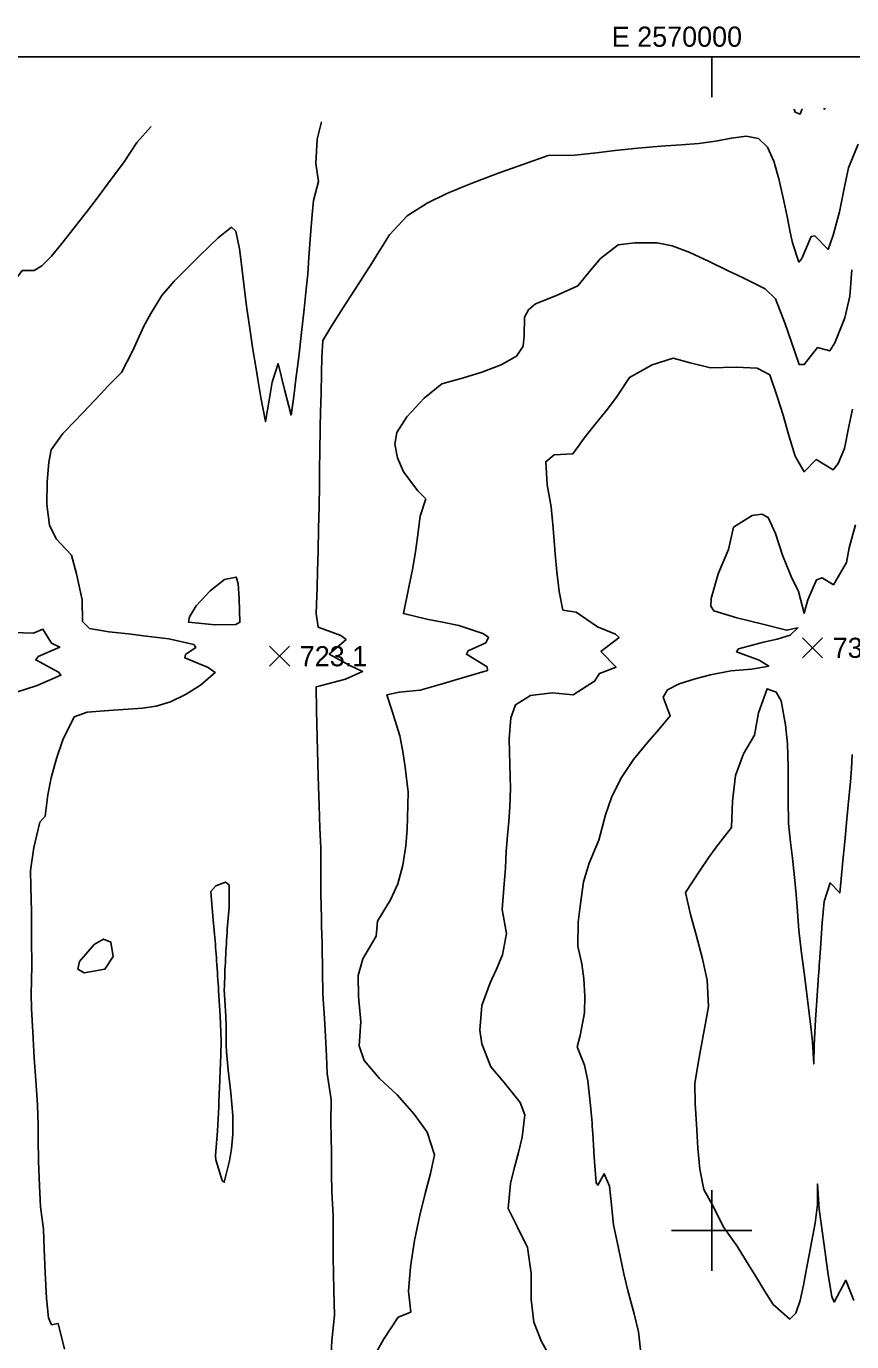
# Model space of a CAD drawing. Extents: x 2566079 to 2571326, y 424054 to 426896.
# Drawn here: x 2569490 to 2570104, y 425917 to 426896 of the extents above; entities that cross this region are included whole.
import ezdxf

# ---------------------------------------------------------------- set-up
doc = ezdxf.new("R2010")
doc.units = 0
for name, color, linetype in [('Contour_ADS_Major', 7, 'Continuous'), ('Contour_ADS_Minor', 7, 'Continuous'), ('Contour_ADS_Spot_Elevation', 7, 'Continuous'), ('Contour_ADS_State_Plane_Border', 7, 'Continuous'), ('Contour_ADS_Tick', 7, 'Continuous')]:
    doc.layers.add(name, color=color, linetype=linetype)

# ---------------------------------------------------------------- blocks, each defined once
blk = doc.blocks.new('S890')
at = {"layer": 'Contour_ADS_Tick'}
for p, q in [((0, -0.5), (0, 0.5)), ((-0.5, 0), (0.5, 0))]:
    blk.add_line(p, q, dxfattribs=at)
blk = doc.blocks.new('S750')
at = {"layer": 'Contour_ADS_Spot_Elevation'}
for p, q in [((-0.5, 0.498), (0.5, -0.498)), ((-0.498, -0.5), (0.498, 0.5))]:
    blk.add_line(p, q, dxfattribs=at)

msp = doc.modelspace()

# ---------------------------------------------------------------- linework, layer by layer
at = {"layer": 'Contour_ADS_Major'}
for points in [[(2569582.66, 426821.92), (2569572.1, 426809.88), (2569562, 426794.76), (2569552.24, 426781.55), (2569544.76, 426771.47), (2569537.76, 426762.19), (2569528.08, 426749.94), (2569516.18, 426734.74), (2569508.52, 426725.45), (2569501.28, 426718.14), (2569495.52, 426714.64), (2569486.72, 426714.73), (2569480.41, 426706.26), (2569473.21, 426694.62), (2569463.96, 426679.49), (2569454.21, 426663.45), (2569445.24, 426648.69), (2569437.29, 426635.75), (2569434.53, 426631.41)], [(2570107.12, 426525.37), (2570102.32, 426508.18), (2570100.29, 426497.28), (2570090.65, 426480.65), (2570082.37, 426485.87), (2570078.05, 426484.34), (2570071.67, 426469.57), (2570068.78, 426459.47), (2570064.64, 426475.67), (2570059.19, 426486.97), (2570052.74, 426502.72), (2570047.41, 426518.79), (2570042.09, 426530.89), (2570037.29, 426533.31), (2570030.17, 426532.38), (2570016.35, 426523.68), (2570012.52, 426506.83), (2570004.76, 426488.72), (2569999.65, 426470.57), (2569999.44, 426464.75), (2570001.54, 426461.17), (2570018.68, 426456.18), (2570038.05, 426451.34), (2570055.76, 426446.84), (2570064.26, 426448.59), (2570058.38, 426443.29), (2570048.7, 426440.29), (2570038.58, 426438.04), (2570020.06, 426433.05), (2570018.41, 426430.88), (2570035.43, 426424.44), (2570042.51, 426420.21), (2570029.91, 426417.98), (2570014.18, 426416.52), (2569999.15, 426413.54), (2569987.7, 426410.75), (2569975.82, 426407.02), (2569967.05, 426402.4), (2569963.91, 426397.09), (2569969.05, 426383.2), (2569960.7, 426372.88), (2569952.14, 426363.3), (2569941.91, 426350.7), (2569932.39, 426336.52), (2569925.45, 426322.22), (2569920.96, 426309.42), (2569916.1, 426290.63), (2569908.68, 426273.47), (2569904.6, 426259.45), (2569902.03, 426241.54), (2569900.53, 426229.44), (2569900.28, 426211.65), (2569903.31, 426198.48), (2569904.69, 426187.43), (2569905.44, 426174.38), (2569905.24, 426161.93), (2569902.14, 426145.04), (2569899.79, 426136.61), (2569905.4, 426123.02), (2569907.81, 426111.48), (2569909.86, 426093.09)], [(2569479.69, 426445.26), (2569495.15, 426444.69), (2569502.07, 426447.75), (2569508.42, 426437.31), (2569514.67, 426434.18), (2569498.58, 426427.32), (2569496.72, 426424.79), (2569513.76, 426415.67), (2569515.44, 426413.39), (2569497.72, 426405.76), (2569481.61, 426400.43)], [(2569911.43, 426072.18), (2569912.44, 426054.5), (2569913.89, 426035.45), (2569915.24, 426033.6), (2569920.05, 426042.2), (2569923.8, 426032.86), (2569925.23, 426021.36), (2569927, 426004.26), (2569929.52, 425991.51), (2569931.76, 425980.91), (2569934.63, 425967.81), (2569937.6, 425955.23), (2569942.4, 425937.97), (2569945.45, 425924.57), (2569947.61, 425906.62)]]:
    msp.add_lwpolyline(points, dxfattribs=at)
msp.add_arc((2569084.33, 426020.59), 828.71, 3.56903, 5.01882, dxfattribs=at)
at = {"layer": 'Contour_ADS_Minor'}
msp.add_line((2569638.3, 426159.62), (2569637.12, 426179.21), dxfattribs=at)
for points in [[(2570067.45, 426834.97), (2570065.76, 426831.1), (2570062.22, 426832.51), (2570061.32, 426834.81)], [(2570084.69, 426835.44), (2570083.91, 426834.76), (2570083.13, 426835.39)], [(2569709.55, 426825.34), (2569706.38, 426812.32), (2569705.36, 426794.34), (2569707.35, 426780.87), (2569703.51, 426766.87), (2569702.55, 426756.44), (2569701.59, 426744.3), (2569700.16, 426724.67), (2569699.23, 426712.03), (2569698.14, 426700.72), (2569696.6, 426685.76), (2569694.69, 426668.47), (2569692.55, 426650.37), (2569690.49, 426633.69), (2569688.84, 426620.81), (2569686.88, 426607.03), (2569681.86, 426626.19), (2569677.17, 426645.42), (2569672.83, 426631.49), (2569670.52, 426618.05), (2569667.89, 426602.13), (2569664.32, 426620.03), (2569662.13, 426633.59), (2569660.55, 426642.89), (2569658.45, 426655.85), (2569656.07, 426671.47), (2569653.74, 426688.18), (2569651.71, 426704.47), (2569649.98, 426719.1), (2569648.46, 426730.9), (2569645.67, 426743.9), (2569642.4, 426746.85), (2569632.52, 426739.01), (2569626.69, 426733.27), (2569618.02, 426724.8), (2569608.28, 426715.25), (2569599.81, 426706.79), (2569590.61, 426696.16), (2569582.46, 426682.67), (2569577.26, 426673.22), (2569568.95, 426655.09), (2569560.71, 426638.74), (2569550.56, 426628.84), (2569545.23, 426622.82), (2569536.37, 426613.46), (2569526, 426602.76), (2569516.91, 426593.4), (2569508.13, 426581.06), (2569506.43, 426571.94), (2569505.13, 426557.37), (2569504.96, 426540.34), (2569507.06, 426525.14), (2569512.01, 426514.94), (2569523.41, 426502.63), (2569527.04, 426488.86), (2569531.19, 426469.48), (2569531.45, 426453.39), (2569536.86, 426448.02), (2569551.26, 426445.57), (2569565.76, 426444.11), (2569578.84, 426442.37), (2569595.92, 426440.33), (2569614.44, 426436.28), (2569616.03, 426434.05), (2569608.12, 426428.66), (2569607.76, 426426.25), (2569625.14, 426419.14), (2569630.37, 426415.49), (2569619.34, 426405.93), (2569608.68, 426399.17), (2569597.19, 426393.46), (2569586.44, 426390.2), (2569576.17, 426388.8), (2569565.64, 426388.17), (2569554.47, 426387.43), (2569535.06, 426385.81), (2569525.34, 426382.45), (2569517.02, 426365.35), (2569512.15, 426351.38), (2569508.17, 426336.97), (2569505.86, 426324.38), (2569503.85, 426308.38), (2569499.74, 426303.87), (2569495.3, 426285.04), (2569492.9, 426267.88), (2569493.15, 426256.06), (2569493.47, 426237.45)], [(2570108.97, 426808.71), (2570101.79, 426791.01), (2570098.87, 426776.97), (2570095.22, 426758.32), (2570090.35, 426741.04), (2570086.69, 426730.37), (2570076.82, 426740.4), (2570074.1, 426740.09), (2570067.15, 426723.68), (2570064.92, 426720.9), (2570060.11, 426735.18), (2570058.53, 426743.19), (2570056.2, 426754.8), (2570053.24, 426768.67), (2570049.9, 426783.02), (2570046.2, 426796.11), (2570041.45, 426806.55), (2570034.8, 426812.99), (2570025.65, 426814.68), (2570014.66, 426813.23), (2570002.73, 426810.86), (2569990.5, 426809.29), (2569977.32, 426808.32), (2569962.26, 426807.29), (2569945.03, 426805.71), (2569928.04, 426803.88), (2569914.34, 426802.3), (2569898.1, 426800.6), (2569878.29, 426800.27), (2569860.04, 426793.89), (2569842.52, 426787.54)], [(2569802.21, 426771.66), (2569788.16, 426764.76), (2569773.31, 426755.29), (2569760.2, 426741.21), (2569754.76, 426732.5), (2569746.97, 426720.11), (2569736.69, 426704.12), (2569725.9, 426687.48), (2569717.13, 426673.84), (2569710.37, 426662.44), (2569709.77, 426650.2), (2569709.51, 426638.17), (2569709.18, 426623.45), (2569708.86, 426609.28), (2569708.58, 426598.05), (2569708.2, 426579.13), (2569708.06, 426567.83), (2569707.9, 426554.51), (2569707.67, 426539.27), (2569707.33, 426522.49), (2569706.93, 426505.67), (2569706.53, 426490.63), (2569706.2, 426478.81), (2569705.63, 426459.22), (2569707.14, 426449.07), (2569723.86, 426442.86), (2569727.78, 426439.87), (2569715.29, 426428.99), (2569730.49, 426420.67), (2569740.12, 426416.15), (2569727.43, 426410.32), (2569708.41, 426405.52), (2569705.47, 426404.64), (2569705.77, 426387.6), (2569706.04, 426376.8), (2569706.47, 426357.04), (2569706.91, 426338.45), (2569707.21, 426330.5), (2569707.73, 426316.33), (2569708.35, 426299.54), (2569708.89, 426284.93), (2569708.99, 426264.94), (2569709.11, 426250.32), (2569709.45, 426232.62)], [(2570104.36, 426715.06), (2570102.83, 426695.65), (2570099.14, 426679.48), (2570091.73, 426660.91), (2570087.85, 426654.75), (2570078.86, 426657.27), (2570068.92, 426644.58), (2570065.21, 426644.58), (2570058.84, 426662.76), (2570054.59, 426675.08), (2570047.51, 426693.67), (2570039.93, 426701.03), (2570023.42, 426709.22), (2570011.67, 426714.75), (2569998.05, 426721.43), (2569983.84, 426728.04), (2569970.55, 426733.03), (2569959.37, 426735.33), (2569942.68, 426735.32), (2569930.38, 426733.76), (2569917.22, 426723.58), (2569910.29, 426715.49), (2569900.27, 426703.37), (2569884.55, 426696.16), (2569868.88, 426689.84), (2569863.63, 426685.35), (2569860.7, 426679.86), (2569860.34, 426666.04), (2569859.6, 426658.33), (2569854.58, 426650.9), (2569843.38, 426644.32), (2569828.89, 426638.89), (2569815.16, 426634.84), (2569798.99, 426630.36), (2569785.9, 426619.54), (2569773.13, 426605.84), (2569765.51, 426594.09), (2569764.08, 426585.49), (2569766.12, 426575.22), (2569770.66, 426564.81), (2569781.3, 426550.59), (2569787.13, 426544.55), (2569783.05, 426531.88), (2569780.86, 426516.21), (2569779.46, 426505.19), (2569777.13, 426492.03), (2569774.42, 426478.82), (2569770.44, 426459.26), (2569787.97, 426455.02), (2569799.66, 426452.95), (2569811.64, 426450.36), (2569829.58, 426444.33), (2569833.85, 426441.58), (2569831.8, 426437.54), (2569818.59, 426431.45), (2569817.37, 426428.93), (2569832.91, 426419.58), (2569833.18, 426416.99), (2569816.9, 426412.08), (2569798.58, 426406.81), (2569783.07, 426402.33), (2569767.38, 426400.83), (2569758.23, 426398.87), (2569762.12, 426386.71), (2569767.71, 426368.28), (2569769.99, 426356.52), (2569771.74, 426344.9), (2569773.94, 426326.23), (2569773.61, 426307.51), (2569773.18, 426298.67), (2569772.18, 426286.27), (2569770.1, 426271.97), (2569766.38, 426257.99), (2569760.88, 426246.21), (2569751.12, 426230.34), (2569750.28, 426218.99), (2569740.23, 426202.21), (2569736.76, 426189.8), (2569737.03, 426174.1), (2569738.8, 426155.64), (2569737.44, 426137.51), (2569741.28, 426126.63), (2569752.78, 426113.18), (2569765.83, 426100.93), (2569778.6, 426086.6)], [(2570104.77, 426611.42), (2570102.21, 426598.45), (2570098.82, 426582.13), (2570094.19, 426571.05), (2570090.4, 426566.29), (2570077.83, 426574.01), (2570068.81, 426564.78), (2570062.23, 426576.36), (2570057.53, 426591.94), (2570053.23, 426607.02), (2570048.77, 426620.94), (2570043.33, 426636.87), (2570033.82, 426641.84), (2570018.33, 426642.73), (2569999.12, 426642.12), (2569983.87, 426645.89), (2569971.25, 426649.3), (2569955.58, 426644.45), (2569938.89, 426635.07), (2569929.67, 426621.14), (2569922.35, 426611.5), (2569913.58, 426600.6), (2569905.82, 426590.85), (2569896.5, 426578.11), (2569882.73, 426577.48), (2569876.41, 426572.25), (2569877.4, 426555.09), (2569880.54, 426538.75), (2569882.08, 426522.94), (2569883.58, 426503.61), (2569884.69, 426490.37), (2569886.56, 426475.67), (2569889.3, 426461.86), (2569899.15, 426460.36), (2569915.03, 426449.46), (2569928.39, 426443.89), (2569931.11, 426441.34), (2569917.51, 426431), (2569928.82, 426419.38), (2569916.36, 426414.67), (2569912.82, 426408.88), (2569896.94, 426398.66), (2569881.21, 426400.13), (2569865.06, 426398.32), (2569853.85, 426391.4), (2569850.44, 426381.6), (2569849.32, 426365.75), (2569849.63, 426346.89), (2569850.11, 426329.08), (2569849.81, 426315.36), (2569848.92, 426304.44), (2569847.89, 426293.99), (2569847.08, 426282.26), (2569846.39, 426269.84), (2569845.61, 426257.93)], [(2570079.59, 426189.88), (2570078.29, 426171.27), (2570077.25, 426156.69), (2570076.27, 426137.93), (2570076.03, 426123.97), (2570075.16, 426140.49), (2570073.89, 426151.53), (2570072.34, 426163.63), (2570070.47, 426178.25), (2570068.75, 426191.85), (2570066.71, 426208.51), (2570064.92, 426223.56), (2570063.6, 426240.63), (2570062.8, 426250.18), (2570061.56, 426263.1), (2570060.09, 426277.08), (2570058.74, 426289.06), (2570057.21, 426303.03), (2570056.95, 426320.77), (2570057.04, 426333.19), (2570057.03, 426345.1), (2570056.35, 426362.35), (2570055.04, 426376.31), (2570051.65, 426394.32), (2570048.01, 426400.84), (2570041.22, 426403.26), (2570034.93, 426385.36), (2570031.83, 426368.72), (2570023.62, 426354.73), (2570017.67, 426338.77), (2570015.61, 426319.62), (2570014.64, 426299.93), (2570003.25, 426285.42), (2569997.64, 426277.45), (2569991.43, 426268.24), (2569980.48, 426251.56), (2569984.28, 426235.13), (2569988.44, 426220.01), (2569993.1, 426202.2), (2569996.74, 426186.23), (2569997.71, 426166.84), (2569995.9, 426157.15), (2569993.39, 426143.62), (2569990.78, 426128.81), (2569987.49, 426109.66), (2569987.69, 426094.2), (2569988.58, 426079.13), (2569989.76, 426061.26), (2569991.08, 426045.69), (2569994.25, 426030.55), (2570000.25, 426019.26), (2570009.15, 426002.21), (2570018.88, 425988.22), (2570028.02, 425973.75), (2570033.29, 425964.92), (2570039.23, 425955.12), (2570045.84, 425944.91), (2570058.27, 425933.97), (2570062.64, 425938.29), (2570065.83, 425947.76), (2570068.3, 425959.25), (2570070.42, 425970.13), (2570073.67, 425987.13), (2570077.12, 426005.53), (2570078.8, 426019.43), (2570078.69, 426034.65), (2570079.95, 426015.9), (2570082.4, 425998.03), (2570084.41, 425983.69), (2570086.8, 425966.92), (2570089.52, 425950.87), (2570091.13, 425946.64), (2570099.84, 425962.89), (2570105.83, 425947.85)], [(2570104.58, 426354.36), (2570104.05, 426343.88), (2570103.27, 426333.91), (2570102.14, 426321.89), (2570100.63, 426306.29), (2570099.01, 426289.54), (2570097.63, 426275.05), (2570096.03, 426256.38), (2570095.4, 426251.25), (2570088.12, 426258.76), (2570083.69, 426244.82), (2570082.24, 426229.03), (2570080.95, 426209.96), (2570080.27, 426199.92)], [(2569639.35, 426224.25), (2569640.73, 426240.64), (2569640.79, 426257.19), (2569638.11, 426259.17), (2569630.8, 426256.53), (2569627.09, 426252.31), (2569628.63, 426233.88), (2569629.89, 426220.69)], [(2569845.61, 426257.93), (2569844.06, 426238.84), (2569847.12, 426221.07), (2569844.23, 426205.09), (2569839.83, 426194.5), (2569835.15, 426184.25), (2569828.75, 426167.5), (2569827.41, 426149.2), (2569828.78, 426138.93), (2569835.59, 426121.81), (2569845.42, 426110.09), (2569857.3, 426095.28), (2569860.78, 426086.12), (2569858.87, 426069.54), (2569856.17, 426058.01), (2569853.05, 426046.06), (2569850.17, 426034.87), (2569848.59, 426016.27), (2569855.49, 426002.49), (2569862.76, 425987.27), (2569865.51, 425968.22), (2569865.7, 425948.54), (2569867.65, 425931.76), (2569873.13, 425917.74), (2569880.37, 425904.06)], [(2569709.66, 426222.17), (2569709.88, 426211.73), (2569710.24, 426193.42), (2569710.52, 426176.2), (2569711.85, 426157.78), (2569712.49, 426144.71), (2569713.12, 426129.79), (2569713.62, 426116.94), (2569716.7, 426097.57), (2569716.56, 426079.79), (2569716.79, 426070.48), (2569716.9, 426057.09), (2569716.98, 426042.16), (2569717.16, 426028.96), (2569718.26, 426010.95), (2569718.14, 425994.54), (2569718.09, 425980.17), (2569718.33, 425968.28), (2569718.66, 425955.38), (2569719.11, 425937.01), (2569717.08, 425917.75), (2569716.4, 425902.97)], [(2569493.7, 426216.14), (2569493.75, 426197.62), (2569493.57, 426185.56), (2569493.44, 426176.45), (2569493.68, 426165.03), (2569494.53, 426147.77), (2569495.68, 426128.24), (2569496.71, 426111.78), (2569498.07, 426093.53), (2569498.44, 426078.05), (2569498.54, 426067.77), (2569498.91, 426051.6), (2569499.5, 426033.25), (2569500.22, 426017.61), (2569502.52, 426001.02), (2569503.12, 425986.19), (2569503.73, 425968.81), (2569504.76, 425949.47), (2569506.33, 425934.92), (2569508.52, 425929.78), (2569513.52, 425930.61), (2569518.25, 425911.56)], [(2569632.91, 426178.32), (2569634.1, 426159.68), (2569634.84, 426141.05), (2569634.49, 426130.53), (2569633.81, 426112.9)], [(2569630.82, 426052.52), (2569635.5, 426037.19), (2569637.05, 426035.83), (2569641.06, 426051.73), (2569642.46, 426060.78), (2569643.45, 426071.72), (2569643.44, 426085.51), (2569642.08, 426102.33), (2569639.97, 426119.42), (2569638.73, 426132.92)], [(2569632.95, 426092.11), (2569632.1, 426074.2), (2569630.53, 426055.79), (2569630.82, 426052.52), (2569630.82, 426052.52)], [(2569778.6, 426086.6), (2569788.23, 426073.11), (2569793.52, 426056.32), (2569790.55, 426042.43), (2569786.63, 426027.62), (2569782.59, 426011.26), (2569778.68, 425992.56), (2569775.73, 425972.99), (2569774.38, 425954.83), (2569775.93, 425939.19), (2569766.7, 425935.38), (2569755.74, 425918.92), (2569750.27, 425909.15)]]:
    msp.add_lwpolyline(points, dxfattribs=at)
for points in [[(2569647.38, 426481.59), (2569645.9, 426486.36), (2569637.3, 426484.7), (2569626.68, 426476.24), (2569616.18, 426465.09), (2569611.2, 426456.79), (2569610.6, 426452.77), (2569630.32, 426450.84), (2569645.82, 426451.02), (2569648.72, 426452.73), (2569648.2, 426470.3), (2569647.38, 426481.59)], [(2569528.09, 426194.62), (2569529.26, 426200.32), (2569540.22, 426213), (2569547.26, 426216.95), (2569552.63, 426214.72), (2569554.47, 426204.06), (2569548.3, 426194.59), (2569532.74, 426191.87), (2569528.09, 426194.62)]]:
    msp.add_lwpolyline(points, close=True, dxfattribs=at)
for centre, radius, start, end in [((2570240.36, 425701.55), 1156.57, 110.11948, 111.22666), ((2570001.19, 426316.08), 497.14, 111.17547, 113.59372), ((2566523.97, 426194.74), 2969.8, 0.4128, 0.82395), ((2585260.15, 426539.89), 15553.74, 181.131992, 181.170494), ((2567881.71, 426078.95), 1753.92, 3.97849, 4.63533), ((2570710.05, 426151.71), 1073.16, 176.12403, 177.29629), ((2565356.3, 425900.21), 4285.64, 3.72075, 4.01984), ((2570446.75, 426156.82), 809.94, 176.77905, 178.41608), ((2561454.5, 426779.09), 8645.19, 356.091981, 356.158672), ((2569112.51, 426144.28), 526.01, 0.21693, 1.6713), ((2569905.97, 426143.8), 267.46, 179.47095, 182.33146), ((2564150.79, 426329.3), 5487.29, 357.52262, 357.73988)]:
    msp.add_arc(centre, radius, start, end, dxfattribs=at)
at = {"layer": 'Contour_ADS_State_Plane_Border'}
msp.add_line((2570000, 426843.74), (2570000, 426873.74), dxfattribs=at)
msp.add_lwpolyline([(2566079.33, 424077.11), (2571302.93, 424077.11), (2571302.93, 426873.74), (2566079.33, 426873.74), (2566079.33, 424077.11)], close=True, dxfattribs=at)

# ---------------------------------------------------------------- block references
at = {"layer": 'Contour_ADS_Spot_Elevation', "xscale": 15, "yscale": 15}
for p in [(2569678.32, 426427.51), (2570075.09, 426433.76)]:
    msp.add_blockref('S750', p, dxfattribs=at)
at = {"layer": 'Contour_ADS_Tick', "xscale": 60, "yscale": 60}
msp.add_blockref('S890', (2570000, 426000), dxfattribs=at)

# ---------------------------------------------------------------- texts
at = {"layer": 'Contour_ADS_Spot_Elevation'}
for s, p in [('723.1', (2569693.32, 426420.01)), ('730.8', (2570090.09, 426426.26))]:
    msp.add_text(s, height=15, dxfattribs=at).set_placement(p)
at = {"layer": 'Contour_ADS_State_Plane_Border'}
msp.add_text(' E 2570000', height=15, dxfattribs=at).set_placement((2569920, 426881.24))

doc.saveas('drawing.dxf')
